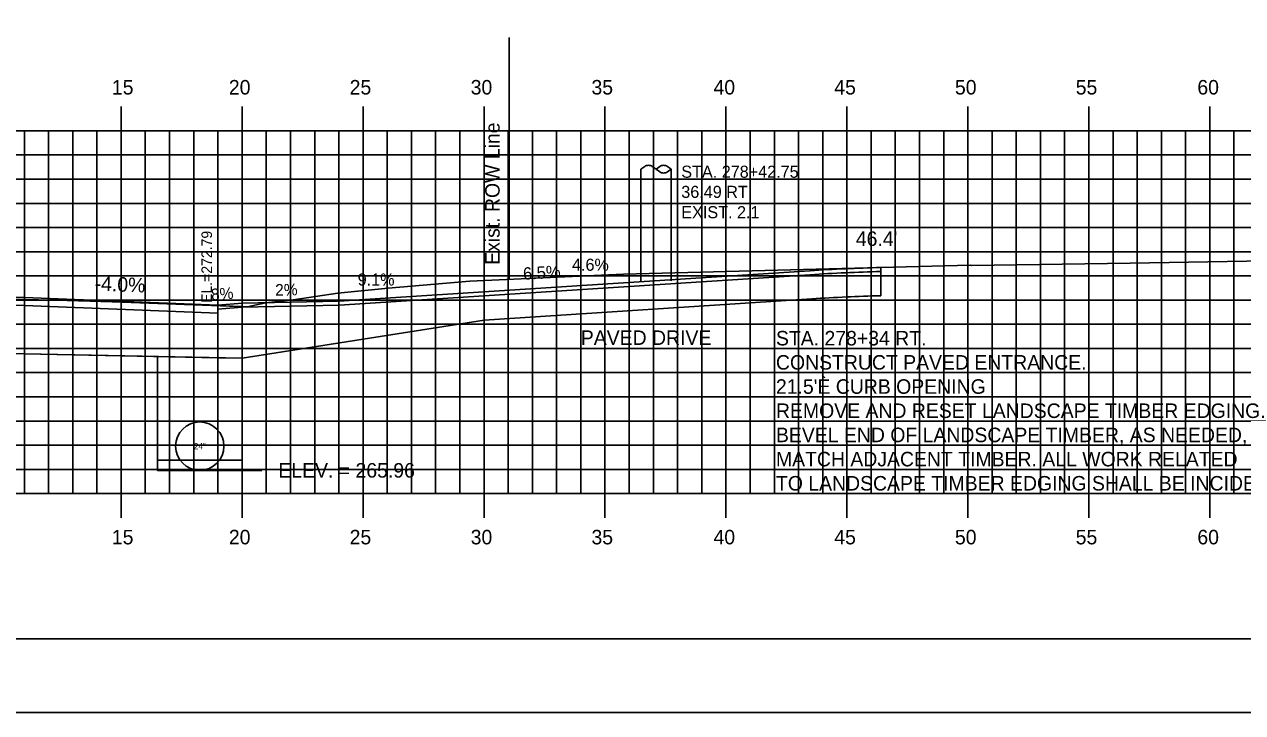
# Model space of a CAD drawing. Extents: x 854676 to 854846, y 366268 to 366378.
# Drawn here: x 854770.1 to 854820.5, y 366268.2 to 366296.6 of the extents above; entities that cross this region are included whole.
import ezdxf

# ---------------------------------------------------------------- set-up
doc = ezdxf.new("R2010")
doc.units = 0
for name, color, linetype in [('ANNOTATION', 7, 'Continuous'), ('BORDER', 7, 'Continuous'), ('D_Roadway_Drive_Gravel_RT', 7, 'Continuous'), ('D_Roadway_Drive_SubGrade', 7, 'Continuous'), ('D_Roadway_Edge_Shoulder', 7, 'Continuous'), ('D_Roadway_SubGrade', 7, 'Continuous'), ('D_Text_Monospaced', 7, 'Continuous'), ('D_Text_Standard', 7, 'Continuous'), ('E_ROW_Line', 7, 'Continuous'), ('H_V ANNOTATION', 7, 'Continuous'), ('JUNK COM EXC', 7, 'Continuous'), ('junk strct exc', 7, 'Continuous'), ('MAJOR', 7, 'Continuous'), ('MINOR', 7, 'Continuous'), ('PDRAIN', 7, 'Continuous'), ('PLOT BOUNDARY', 7, 'Continuous'), ('S_Roadway_Centerline', 7, 'Continuous'), ('S_Utilities_Pole_Power', 7, 'Continuous'), ('TEXT', 7, 'Continuous')]:
    doc.layers.add(name, color=color, linetype=linetype)

msp = doc.modelspace()

# ---------------------------------------------------------------- linework, layer by layer
at = {"layer": 'BORDER'}
msp.add_line((854684.107, 366271.236), (854844.107, 366271.236), dxfattribs=at)
at = {"layer": 'D_Roadway_Drive_Gravel_RT'}
for p, q in [((854783.107, 366285.185), (854802.58, 366286.451)), ((854783.114, 366285.019), (854802.591, 366286.285)), ((854789.106, 366284.406), (854802.656, 366285.287)), ((854778.106, 366284.858), (854779.115, 366284.939)), ((854778.107, 366285.025), (854779.107, 366285.105)), ((854778.107, 366284.692), (854778.107, 366285.025)), ((854779.107, 366285.105), (854783.107, 366285.185)), ((854779.11, 366284.939), (854783.114, 366285.019)), ((854783.107, 366285.185), (854783.107, 366285.185))]:
    msp.add_line(p, q, dxfattribs=at)
for radius, start, end in [(75, 91.47757, 93.71899), (74.833, 91.48086, 93.71899), (73.833, 91.50092, 93.71916)]:
    msp.add_arc((854807.445, 366211.609), radius, start, end, dxfattribs=at)
at = {"layer": 'D_Roadway_Drive_SubGrade'}
for p, q in [((854805.511, 366286.584), (854805.511, 366285.417)), ((854779.107, 366282.832), (854789.106, 366284.406)), ((854778.107, 366282.852), (854779.107, 366282.832))]:
    msp.add_line(p, q, dxfattribs=at)
at = {"layer": 'D_Roadway_Edge_Shoulder'}
msp.add_lwpolyline([(854740.106, 366285.281), (854748.106, 366285.601), (854759.106, 366285.566), (854770.106, 366285.346), (854778.107, 366285.025)], dxfattribs=at)
at = {"layer": 'D_Roadway_SubGrade'}
for points in [[(854748.106, 366283.267), (854748.106, 366285.267), (854759.106, 366285.232), (854770.106, 366285.012), (854770.106, 366283.012), (854759.106, 366283.232)], [(854770.106, 366285.012), (854778.107, 366284.692), (854778.107, 366282.852), (854770.106, 366283.012)]]:
    msp.add_lwpolyline(points, close=True, dxfattribs=at)
at = {"layer": 'D_Text_Standard'}
msp.add_lwpolyline([(854779.107, 366278.196), (854779.245, 366278.196), (854779.925, 366278.196)], dxfattribs=at)
at = {"layer": 'E_ROW_Line'}
msp.add_line((854790.152, 366286.093), (854790.152, 366296.093), dxfattribs=at)
at = {"layer": 'JUNK COM EXC'}
for points in [[(854805.511, 366285.417), (854805.511, 366286.584), (854794.872, 366286.31), (854788.523, 366286.018), (854785.139, 366285.725), (854783.057, 366285.522), (854781.22, 366285.244), (854780.092, 366285.127), (854779.318, 366284.958), (854779.107, 366284.966), (854779.107, 366282.832), (854789.106, 366284.406), (854802.655, 366285.287)], [(854735.101, 366285.679), (854735.101, 366284.789), (854739.106, 366284.709), (854739.106, 366283.087), (854748.106, 366283.267), (854759.106, 366283.232), (854770.106, 366283.012), (854779.107, 366282.832), (854779.107, 366284.966), (854773.78, 366285.165), (854773.739, 366285.161), (854771.879, 366285.217), (854761.239, 366285.468), (854759.829, 366285.5), (854758.547, 366285.5), (854748.52, 366285.618), (854747.7, 366285.585), (854741.471, 366285.366), (854740.556, 366285.66), (854740.379, 366285.723), (854739.868, 366285.754), (854736.899, 366285.86), (854735.383, 366285.709), (854735.101, 366285.679)], [(854802.656, 366285.287), (854802.656, 366285.287)]]:
    msp.add_lwpolyline(points, dxfattribs=at)
for start, end in [(93.71883, 93.71916), (91.50092, 93.71863)]:
    msp.add_arc((854807.445, 366211.609), 73.833, start, end, dxfattribs=at)
at = {"layer": 'junk strct exc'}
msp.add_lwpolyline([(854775.607, 366282.902), (854775.607, 366278.616), (854779.107, 366278.616), (854779.107, 366282.832)], close=True, dxfattribs=at)
at = {"layer": 'MAJOR'}
for p, q in [((854774.106, 366293.238), (854774.106, 366292.236)), ((854779.106, 366293.238), (854779.106, 366292.236)), ((854784.106, 366293.238), (854784.106, 366292.236)), ((854789.106, 366293.238), (854789.106, 366292.236)), ((854794.106, 366293.238), (854794.106, 366292.236)), ((854799.106, 366293.238), (854799.106, 366292.236)), ((854804.106, 366293.238), (854804.106, 366292.236)), ((854809.106, 366293.238), (854809.106, 366292.236)), ((854814.106, 366293.238), (854814.106, 366292.236)), ((854819.106, 366293.238), (854819.106, 366292.236)), ((854689.106, 366292.236), (854829.106, 366292.236)), ((854689.106, 366292.236), (854829.106, 366292.236)), ((854774.106, 366277.236), (854774.106, 366292.236)), ((854779.106, 366277.236), (854779.106, 366292.236)), ((854784.106, 366277.236), (854784.106, 366292.236)), ((854789.106, 366277.236), (854789.106, 366292.236)), ((854794.106, 366277.236), (854794.106, 366292.236)), ((854799.106, 366277.236), (854799.106, 366292.236)), ((854804.106, 366277.236), (854804.106, 366292.236)), ((854809.106, 366277.236), (854809.106, 366292.236)), ((854814.106, 366277.236), (854814.106, 366292.236)), ((854819.106, 366277.236), (854819.106, 366292.236)), ((854689.106, 366287.236), (854829.106, 366287.236)), ((854689.106, 366282.236), (854829.106, 366282.236)), ((854689.106, 366277.236), (854829.106, 366277.236)), ((854689.106, 366277.236), (854829.106, 366277.236)), ((854774.106, 366276.234), (854774.106, 366277.236)), ((854779.106, 366276.234), (854779.106, 366277.236)), ((854784.106, 366276.234), (854784.106, 366277.236)), ((854789.106, 366276.234), (854789.106, 366277.236)), ((854794.106, 366276.234), (854794.106, 366277.236)), ((854799.106, 366276.234), (854799.106, 366277.236)), ((854804.106, 366276.234), (854804.106, 366277.236)), ((854809.106, 366276.234), (854809.106, 366277.236)), ((854814.106, 366276.234), (854814.106, 366277.236)), ((854819.106, 366276.234), (854819.106, 366277.236))]:
    msp.add_line(p, q, dxfattribs=at)
at = {"layer": 'MINOR'}
for p, q in [((854770.106, 366277.236), (854770.106, 366292.236)), ((854771.106, 366277.236), (854771.106, 366292.236)), ((854772.106, 366277.236), (854772.106, 366292.236)), ((854773.106, 366277.236), (854773.106, 366292.236)), ((854775.106, 366277.236), (854775.106, 366292.236)), ((854776.106, 366277.236), (854776.106, 366292.236)), ((854777.106, 366277.236), (854777.106, 366292.236)), ((854778.106, 366277.236), (854778.106, 366292.236)), ((854780.106, 366277.236), (854780.106, 366292.236)), ((854781.106, 366277.236), (854781.106, 366292.236)), ((854782.106, 366277.236), (854782.106, 366292.236)), ((854783.106, 366277.236), (854783.106, 366292.236)), ((854785.106, 366277.236), (854785.106, 366292.236)), ((854786.106, 366277.236), (854786.106, 366292.236)), ((854787.106, 366277.236), (854787.106, 366292.236)), ((854788.106, 366277.236), (854788.106, 366292.236)), ((854790.106, 366277.236), (854790.106, 366292.236)), ((854791.106, 366277.236), (854791.106, 366292.236)), ((854792.106, 366277.236), (854792.106, 366292.236)), ((854793.106, 366277.236), (854793.106, 366292.236)), ((854795.106, 366277.236), (854795.106, 366292.236)), ((854796.106, 366277.236), (854796.106, 366292.236)), ((854797.106, 366277.236), (854797.106, 366292.236)), ((854798.106, 366277.236), (854798.106, 366292.236)), ((854800.106, 366277.236), (854800.106, 366292.236)), ((854801.106, 366277.236), (854801.106, 366292.236)), ((854802.106, 366277.236), (854802.106, 366292.236)), ((854803.106, 366277.236), (854803.106, 366292.236)), ((854805.106, 366277.236), (854805.106, 366292.236)), ((854806.106, 366277.236), (854806.106, 366292.236)), ((854807.106, 366277.236), (854807.106, 366292.236)), ((854808.106, 366277.236), (854808.106, 366292.236)), ((854810.106, 366277.236), (854810.106, 366292.236)), ((854811.106, 366277.236), (854811.106, 366292.236)), ((854812.106, 366277.236), (854812.106, 366292.236)), ((854813.106, 366277.236), (854813.106, 366292.236)), ((854815.106, 366277.236), (854815.106, 366292.236)), ((854816.106, 366277.236), (854816.106, 366292.236)), ((854817.106, 366277.236), (854817.106, 366292.236)), ((854818.106, 366277.236), (854818.106, 366292.236)), ((854820.106, 366277.236), (854820.106, 366292.236)), ((854689.106, 366291.236), (854829.106, 366291.236)), ((854689.106, 366290.236), (854829.106, 366290.236)), ((854689.106, 366289.236), (854829.106, 366289.236)), ((854689.106, 366288.236), (854829.106, 366288.236)), ((854689.106, 366286.236), (854829.106, 366286.236)), ((854689.106, 366285.236), (854829.106, 366285.236)), ((854689.106, 366284.236), (854829.106, 366284.236)), ((854689.106, 366283.236), (854829.106, 366283.236)), ((854689.106, 366281.236), (854829.106, 366281.236)), ((854689.106, 366280.236), (854829.106, 366280.236)), ((854689.106, 366279.236), (854829.106, 366279.236)), ((854689.106, 366278.236), (854829.106, 366278.236))]:
    msp.add_line(p, q, dxfattribs=at)
at = {"layer": 'PDRAIN'}
msp.add_lwpolyline([(854775.607, 366282.902), (854775.607, 366278.196), (854779.107, 366278.196), (854779.107, 366282.832)], dxfattribs=at)
msp.add_circle((854777.357, 366279.196), 1, dxfattribs=at)
at = {"layer": 'PLOT BOUNDARY'}
msp.add_lwpolyline([(854676.013, 366268.177), (854846.013, 366268.177), (854846.013, 366378.177), (854676.013, 366378.177)], close=True, dxfattribs=at)
at = {"layer": 'S_Roadway_Centerline'}
msp.add_lwpolyline([(854761.239, 366285.468), (854771.879, 366285.217), (854773.739, 366285.161), (854773.78, 366285.165), (854779.318, 366284.958), (854780.092, 366285.127), (854781.22, 366285.244), (854783.057, 366285.522), (854785.139, 366285.725), (854788.523, 366286.018), (854794.872, 366286.31), (854809.217, 366286.68), (854809.259, 366286.671), (854815.82, 366286.767), (854821.433, 366286.854)], dxfattribs=at)
at = {"layer": 'S_Utilities_Pole_Power'}
for p, q in [((854795.594, 366290.65), (854795.75, 366290.76)), ((854796.062, 366290.76), (854796.218, 366290.65)), ((854796.375, 366290.76), (854796.218, 366290.65)), ((854796.844, 366290.65), (854796.687, 366290.76)), ((854795.594, 366286.03), (854795.59, 366290.65)), ((854796.218, 366290.65), (854796.375, 366290.539)), ((854796.687, 366290.539), (854796.844, 366290.65)), ((854796.844, 366286.03), (854796.84, 366290.65))]:
    msp.add_line(p, q, dxfattribs=at)
for centre, start, end in [((854795.906, 366290.539), 90, 125.2644), ((854795.906, 366290.539), 54.7356, 90), ((854796.531, 366290.539), 90, 125.2644), ((854796.531, 366290.539), 54.7356, 90), ((854796.531, 366290.76), 234.7356, 270), ((854796.531, 366290.76), 270, 305.2644)]:
    msp.add_arc(centre, 0.271, start, end, dxfattribs=at)

# ---------------------------------------------------------------- texts
at = {"layer": 'ANNOTATION'}
for s, height, rotation, p in [('6.5%', 0.51, 3.719, (854790.734, 366286.071)), ('-4.0%', 0.6, 357.7094, (854773.002, 366285.63))]:
    msp.add_text(s, height=height, rotation=rotation, dxfattribs=at).set_placement(p)
for s, p in [('PAVED DRIVE', (854793.107, 366283.381)), ('STA. 278+34 RT.', (854801.173, 366283.361)), ('CONSTRUCT PAVED ENTRANCE.', (854801.173, 366282.361)), ("21.5'È CURB OPENING", (854801.173, 366281.361)), ('REMOVE AND RESET LANDSCAPE TIMBER EDGING.', (854801.173, 366280.361)), ('BEVEL END OF LANDSCAPE TIMBER, AS NEEDED, TO', (854801.173, 366279.361)), ('MATCH ADJACENT TIMBER. ALL WORK RELATED', (854801.173, 366278.361)), ('TO LANDSCAPE TIMBER EDGING SHALL BE INCIDENTAL.', (854801.173, 366277.361))]:
    msp.add_text(s, height=0.6, dxfattribs=at).set_placement(p)
at = {"layer": 'D_Roadway_Drive_Gravel_RT'}
for s, rotation, p in [('8%', 4.5739, (854777.839, 366285.219)), ('2%', 1.1922, (854780.477, 366285.414))]:
    msp.add_text(s, height=0.48, rotation=rotation, dxfattribs=at).set_placement(p)
at = {"layer": 'D_Text_Monospaced'}
for s, height, p in [('STA. 278+42.75', 0.49998, (854797.26, 366290.294)), ('36.49 RT.', 0.5, (854797.26, 366289.46)), ('EXIST. 2.1', 0.5, (854797.26, 366288.62))]:
    msp.add_text(s, height=height, dxfattribs=at).set_placement(p)
at = {"layer": 'D_Text_Standard'}
msp.add_text(' EL.=272.79', height=0.4335, rotation=90, dxfattribs=at).set_placement((854777.861, 366284.957))
for s, p in [("46.4'", (854804.475, 366287.475)), ('ELEV. = 265.96', (854780.605, 366277.896))]:
    msp.add_text(s, height=0.6, dxfattribs=at).set_placement(p)
at = {"layer": 'E_ROW_Line'}
msp.add_text('Exist. ROW Line', height=0.6, rotation=90, dxfattribs=at).set_placement((854789.752, 366286.693))
at = {"layer": 'H_V ANNOTATION'}
for s, p in [('15', (854773.724, 366293.736)), ('20', (854778.56, 366293.736)), ('25', (854783.552, 366293.736)), ('30', (854788.555, 366293.736)), ('35', (854793.547, 366293.736)), ('40', (854798.592, 366293.736)), ('45', (854803.584, 366293.736)), ('50', (854808.571, 366293.736)), ('55', (854813.563, 366293.736)), ('60', (854818.592, 366293.736)), ('15', (854773.724, 366275.136)), ('20', (854778.56, 366275.136)), ('25', (854783.552, 366275.136)), ('30', (854788.555, 366275.136)), ('35', (854793.547, 366275.136)), ('40', (854798.592, 366275.136)), ('45', (854803.584, 366275.136)), ('50', (854808.571, 366275.136)), ('55', (854813.563, 366275.136)), ('60', (854818.592, 366275.136))]:
    msp.add_text(s, height=0.6, dxfattribs=at).set_placement(p)
at = {"layer": 'PDRAIN'}
msp.add_text('24"', height=0.25, dxfattribs=at).set_placement((854777.115, 366279.071))
at = {"layer": 'TEXT'}
for s, p in [('4.6%', (854792.742, 366286.449)), ('9.1%', (854783.884, 366285.836))]:
    msp.add_text(s, height=0.5, dxfattribs=at).set_placement(p)

doc.saveas('drawing.dxf')
